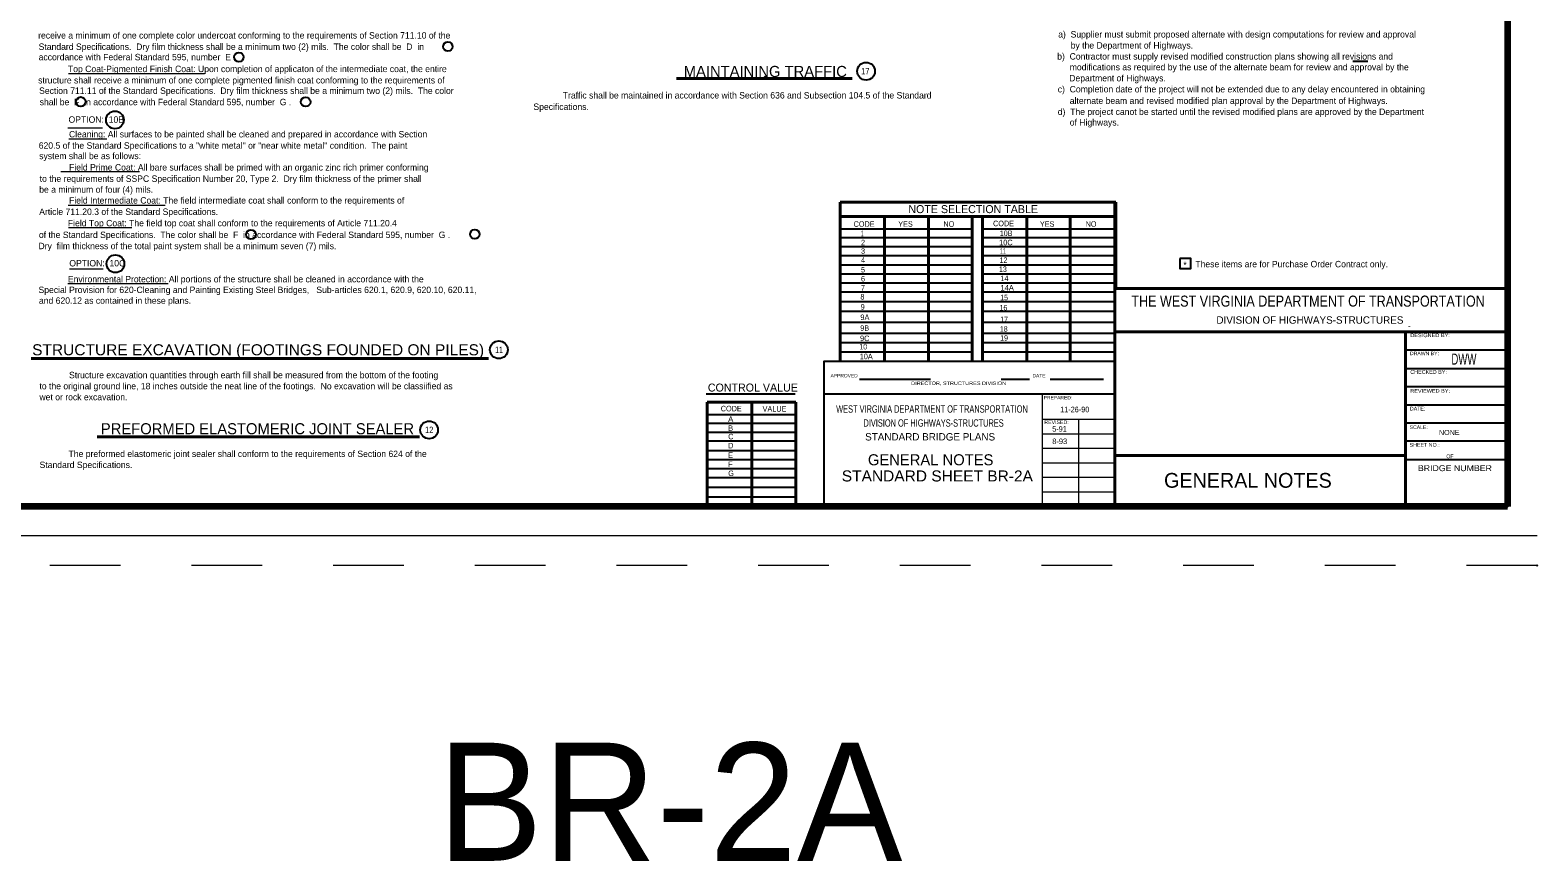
# Model space of a CAD drawing. Extents: x -2.94 to 3.45, y 0.57 to 4.
# Drawn here: x 1.326 to 3.455, y 1.205 to 2.377 of the extents above; entities that cross this region are included whole.
import ezdxf
from ezdxf.enums import TextEntityAlignment as Align

# ---------------------------------------------------------------- set-up
doc = ezdxf.new("R2010")
doc.units = 0
doc.header["$LTSCALE"] = 0.0036
doc.header["$PDMODE"] = 32
doc.header["$PDSIZE"] = 0.0018
doc.linetypes.add('DOTTED', pattern=[1.5, 0.3, -1.2])
doc.linetypes.add('LONG_DASHED', pattern=[7.5, 6, -1.5])
for name, color, linetype, lineweight in [('1', 7, 'Continuous', 13), ('3', 7, 'Continuous', 25), ('61', 7, 'Continuous', 25)]:
    doc.layers.add(name, color=color, linetype=linetype, lineweight=lineweight)

msp = doc.modelspace()

# ---------------------------------------------------------------- linework, layer by layer
at = {"layer": '1', "lineweight": 158}
for p, q in [((3.411833, 3.455), (3.411833, 1.705)), ((3.411833, 1.705), (0.599333, 1.705))]:
    msp.add_line(p, q, dxfattribs=at)
at = {"layer": '1', "lineweight": 25}
for p, q in [((3.273583, 1.9585), (3.273583, 1.959)), ((3.267667, 1.92575), (3.411833, 1.92575)), ((2.446917, 1.910083), (2.857583, 1.910083)), ((3.267667, 1.899833), (3.411833, 1.899833)), ((3.267667, 1.874), (3.411833, 1.874)), ((2.446917, 1.863667), (2.857583, 1.863667)), ((3.267667, 1.8485), (3.411833, 1.8485)), ((3.267667, 1.82275), (3.411833, 1.82275)), ((3.267667, 1.797333), (3.411833, 1.797333)), ((3.267667, 1.771333), (3.411833, 1.771333))]:
    msp.add_line(p, q, dxfattribs=at)
at = {"layer": '1', "lineweight": 40}
for p, q in [((2.857583, 1.951167), (3.411833, 1.951167)), ((3.267667, 1.951167), (3.267667, 1.705)), ((2.857583, 1.77675), (3.267667, 1.77675))]:
    msp.add_line(p, q, dxfattribs=at)
at = {"layer": '1', "linetype": 'DOTTED', "lineweight": 25}
for p, q in [((2.497167, 1.884417), (2.736833, 1.884417)), ((2.766, 1.884417), (2.841333, 1.884417))]:
    msp.add_line(p, q, dxfattribs=at)
at = {"layer": '1'}
for p, q in [((2.755, 1.863667), (2.755, 1.705)), ((2.755, 1.828167), (2.857583, 1.828167)), ((2.80625, 1.828583), (2.80625, 1.705)), ((2.755, 1.807583), (2.857583, 1.807583)), ((2.755, 1.787), (2.857583, 1.787)), ((2.755, 1.7665), (2.857583, 1.7665)), ((2.755, 1.746083), (2.857583, 1.746083)), ((2.755, 1.7255), (2.857583, 1.7255)), ((3.45375, 1.66325), (0.45325, 1.66325))]:
    msp.add_line(p, q, dxfattribs=at)
at = {"layer": '1', "linetype": 'LONG_DASHED'}
msp.add_line((3.45375, 1.621583), (0.45325, 1.621583), dxfattribs=at)
at = {"layer": '1', "lineweight": 40}
msp.add_lwpolyline([(2.857583, 1.705), (2.857583, 2.012667), (3.411833, 2.012667)], dxfattribs=at)
at = {"layer": '1', "lineweight": 25}
msp.add_lwpolyline([(2.446917, 1.705), (2.446917, 1.910083), (2.857583, 1.910083)], dxfattribs=at)
at = {"layer": '1'}
for p in [(2.363917, 2.311083), (3.411833, 1.705), (3.45375, 1.621583)]:
    msp.add_point(p, dxfattribs=at)
at = {"layer": '3'}
msp.add_line((3.193667, 2.333333), (3.2145, 2.333333), dxfattribs=at)
at = {"layer": '3', "lineweight": 13}
for p, q in [((1.380333, 2.316083), (1.572, 2.316083)), ((1.379167, 2.239083), (1.42825, 2.239083)), ((1.380833, 2.223917), (1.434417, 2.223917)), ((1.36925, 2.177417), (1.480417, 2.177417)), ((1.3795, 2.129917), (1.516833, 2.129917)), ((1.38, 2.098583), (1.469667, 2.098583)), ((1.3815, 2.040083), (1.429167, 2.040083)), ((1.37925, 2.019667), (1.521083, 2.019667))]:
    msp.add_line(p, q, dxfattribs=at)
at = {"layer": '3', "lineweight": 40}
for p, q in [((2.23875, 2.308833), (2.486583, 2.308833)), ((1.327667, 1.913917), (1.972917, 1.913917)), ((1.420417, 1.803083), (1.875667, 1.803083))]:
    msp.add_line(p, q, dxfattribs=at)
at = {"layer": '3'}
msp.add_lwpolyline([(2.949333, 2.054917), (2.949333, 2.040667), (2.964917, 2.040667), (2.964917, 2.054917)], close=True, dxfattribs=at)
for centre, radius in [((1.62075, 2.339083), 0.006667), ((1.915833, 2.354), 0.006667), ((2.50625, 2.319167), 0.0125), ((1.397417, 2.276167), 0.006667), ((1.715, 2.275917), 0.006667), ((1.44575, 2.250417), 0.0125), ((1.637833, 2.088583), 0.006667), ((1.953833, 2.089083), 0.006667), ((1.446417, 2.047417), 0.0125), ((1.98775, 1.926083), 0.0125), ((1.889333, 1.812917), 0.0125)]:
    msp.add_circle(centre, radius, dxfattribs=at)
at = {"layer": '61', "lineweight": 40}
for p, q in [((2.469583, 2.134333), (2.469583, 1.910083)), ((2.469583, 2.134333), (2.858667, 2.134333)), ((2.4695, 2.113917), (2.858583, 2.113917)), ((2.532417, 1.910083), (2.532417, 2.11375)), ((2.594583, 1.910083), (2.594583, 2.113917)), ((2.655917, 1.910083), (2.655917, 2.114)), ((2.670417, 1.910083), (2.670417, 2.113833)), ((2.733167, 1.910083), (2.733167, 2.113833)), ((2.794583, 1.910083), (2.794583, 2.113917)), ((2.469583, 2.059833), (2.469583, 2.046667)), ((2.281917, 1.852083), (2.407, 1.852083)), ((2.282, 1.852167), (2.282, 1.705583)), ((2.407, 1.705583), (2.407, 1.852083)), ((2.344833, 1.7055), (2.344833, 1.851833)), ((2.282, 1.797917), (2.282, 1.784833)), ((2.282, 1.7055), (2.407, 1.7055))]:
    msp.add_line(p, q, dxfattribs=at)
at = {"layer": '61', "lineweight": 53}
msp.add_line((2.858583, 2.012667), (2.858583, 2.134333), dxfattribs=at)
at = {"layer": '61'}
for p, q in [((2.655917, 2.09625), (2.469417, 2.09625)), ((2.858583, 2.09625), (2.670333, 2.09625)), ((2.655917, 2.083833), (2.4695, 2.083833)), ((2.656, 2.07125), (2.469583, 2.07125)), ((2.858583, 2.083833), (2.670333, 2.083833)), ((2.858583, 2.07125), (2.670333, 2.07125)), ((2.4695, 2.045833), (2.656, 2.045833)), ((2.656, 2.058833), (2.469583, 2.058833)), ((2.469583, 2.058167), (2.469583, 2.042583)), ((2.858583, 2.058833), (2.670333, 2.058833)), ((2.670333, 2.045833), (2.857583, 2.045833)), ((2.4695, 2.033083), (2.655917, 2.033083)), ((2.469583, 2.0335), (2.469583, 2.020333)), ((2.670333, 2.033083), (2.857583, 2.033083)), ((2.469583, 2.02075), (2.469583, 1.9825)), ((2.469583, 2.020333), (2.655917, 2.020333)), ((2.469583, 2.007583), (2.656, 2.007583)), ((2.469583, 2.007167), (2.469583, 1.994)), ((2.670333, 2.020333), (2.85675, 2.020333)), ((2.670333, 2.007583), (2.858417, 2.007583)), ((2.469583, 1.994), (2.656, 1.994)), ((2.469583, 1.9805), (2.656, 1.9805)), ((2.670333, 1.9805), (2.857583, 1.9805)), ((2.670417, 1.994), (2.857583, 1.994)), ((2.469583, 1.964833), (2.656, 1.964833)), ((2.670333, 1.964833), (2.857583, 1.964833)), ((2.469583, 1.94925), (2.656, 1.94925)), ((2.670333, 1.94925), (2.857583, 1.94925)), ((2.469583, 1.93625), (2.656, 1.93625)), ((2.469583, 1.92325), (2.656, 1.92325)), ((2.670333, 1.93625), (2.857583, 1.93625)), ((2.670333, 1.92325), (2.857583, 1.92325)), ((2.2805, 1.86375), (2.40625, 1.86375)), ((2.407, 1.834333), (2.281833, 1.834333)), ((2.407, 1.821917), (2.281917, 1.821917)), ((2.407, 1.809333), (2.282, 1.809333)), ((2.407, 1.796917), (2.282, 1.796917)), ((2.282, 1.796333), (2.282, 1.780667)), ((2.281917, 1.784), (2.407, 1.784)), ((2.281917, 1.77125), (2.407, 1.77125)), ((2.282, 1.771583), (2.282, 1.7585)), ((2.282, 1.758833), (2.282, 1.720583)), ((2.282, 1.7585), (2.407, 1.7585)), ((2.282, 1.74575), (2.407, 1.74575)), ((2.282, 1.745333), (2.282, 1.732167)), ((2.282, 1.732167), (2.407, 1.732167)), ((2.282, 1.731833), (2.282, 1.705583)), ((2.282, 1.718667), (2.407, 1.718667))]:
    msp.add_line(p, q, dxfattribs=at)

# ---------------------------------------------------------------- texts
at = {"layer": '1'}
for s, height, p in [('Field Top Coat: The field top coat shall conform to the requirements of Article 711.20.4', 0.009083, (1.379333, 2.10025)), ('of the Standard Specifications.  The color shall be  F  in accordance with Federal Standard 595, number  G .', 0.009083, (1.338417, 2.08375)), ('Dry  film thickness of the total paint system shall be a minimum seven (7) mils.', 0.009083, (1.337833, 2.068)), ('OPTION:  10C', 0.009083, (1.381333, 2.043667)), ('Environmental Protection: All portions of the structure shall be cleaned in accordance with the ', 0.009083, (1.379333, 2.021167)), ('Special Provision for 620-Cleaning and Painting Existing Steel Bridges,   Sub-articles 620.1, 620.9, 620.10, 620.11,', 0.009083, (1.337833, 2.006083)), ('and 620.12 as contained in these plans.', 0.009083, (1.338417, 1.990917)), ('DATE:', 0.005335, (3.274083, 1.840333)), ('REVISED:', 0.005335, (2.757917, 1.821167)), ('NONE', 0.007251, (3.315083, 1.805667))]:
    msp.add_text(s, height=height, dxfattribs=at).set_placement(p)
for s, height, width, p in [('THE WEST VIRGINIA DEPARTMENT OF TRANSPORTATION', 0.01558, 0.85, (3.13025, 1.986917)), ('WEST VIRGINIA DEPARTMENT OF TRANSPORTATION', 0.01042, 0.75, (2.599292, 1.83725)), ('DIVISION OF HIGHWAYS-STRUCTURES', 0.01042, 0.75, (2.601542, 1.8175)), ('BRIDGE NUMBER', 0.008416, 1.1, (3.337542, 1.75475))]:
    msp.add_text(s, height=height, dxfattribs=dict(at, width=width)).set_placement(p, align=Align.CENTER)
msp.add_text('DIVISION OF HIGHWAYS-STRUCTURES ', height=0.01042, dxfattribs=at).set_placement((3.134792, 1.962833), align=Align.CENTER)
for s, height, width, p in [('DESIGNED BY:', 0.005335, 1.1, (3.274583, 1.943833)), ('DRAWN BY:', 0.004918, 1.1, (3.274083, 1.918417)), ('DWW', 0.01558, 0.65, (3.332583, 1.905083)), ('CHECKED BY:', 0.005419, 1.05, (3.274583, 1.892)), ('APPROVED', 0.004917, 1.05, (2.456083, 1.887083)), ('DIRECTOR, STRUCTURES DIVISION', 0.004835, 1.2, (2.569917, 1.876417)), ('DATE', 0.004917, 1.05, (2.741167, 1.887083)), ('PREPARED:', 0.004751, 1.1, (2.756917, 1.856)), ('REVIEWED BY:', 0.004835, 1.2, (3.274583, 1.865667)), ('SCALE:', 0.004918, 1.1, (3.273583, 1.814333)), ('SHEET NO.:', 0.005335, 1.05, (3.273583, 1.789083)), ('OF', 0.005419, 0.85, (3.325417, 1.772917))]:
    msp.add_text(s, height=height, dxfattribs=dict(at, width=width)).set_placement(p)
at = {"layer": '3'}
for s, height, p in [('receive a minimum of one complete color undercoat conforming to the requirements of Section 711.10 of the ', 0.009083, (1.337333, 2.36525)), ('a)  Supplier must submit proposed alternate with design computations for review and approval', 0.009083, (2.777417, 2.36675)), ('accordance with Federal Standard 595, number  E .', 0.009083, (1.338, 2.334583)), ('Standard Specifications.  Dry film thickness shall be a minimum two (2) mils.  The color shall be  D  in ', 0.009083, (1.338, 2.34925)), ('b)  Contractor must supply revised modified construction plans showing all revisions and', 0.009083, (2.776083, 2.335583)), ('by the Department of Highways.', 0.009083, (2.795083, 2.351167)), ('Top Coat-Pigmented Finish Coat: Upon completion of applicaton of the intermediate coat, the entire', 0.009083, (1.379417, 2.317917)), ('modifications as required by the use of the alternate beam for review and approval by the', 0.009083, (2.79375, 2.320417)), ('structure shall receive a minimum of one complete pigmented finish coat conforming to the requirements of ', 0.009083, (1.337333, 2.301917)), ('Department of Highways.', 0.009083, (2.793083, 2.304833)), ('Section 711.11 of the Standard Specifications.  Dry film thickness shall be a minimum two (2) mils.  The color', 0.009083, (1.338667, 2.287167)), ('shall be  F  in accordance with Federal Standard 595, number  G .', 0.009083, (1.3395, 2.271167)), ('Traffic shall be maintained in accordance with Section 636 and Subsection 104.5 of the Standard', 0.009083, (2.078, 2.280667)), ('c)  Completion date of the project will not be extended due to any delay encountered in obtaining', 0.009083, (2.776833, 2.28925)), ('alternate beam and revised modified plan approval by the Department of Highways.', 0.009083, (2.79375, 2.273)), ('Specifications.', 0.009083, (2.036583, 2.2645)), ('d)  The project canot be started until the revised modified plans are approved by the Department', 0.009083, (2.776833, 2.257417)), ('OPTION:  10B', 0.009083, (1.38025, 2.246417)), ('Cleaning: All surfaces to be painted shall be cleaned and prepared in accordance with Section', 0.009083, (1.380917, 2.22575)), ('of Highways.', 0.009083, (2.79375, 2.2425)), ('620.5 of the Standard Specifications to a "white metal" or "near white metal" condition.  The paint ', 0.009083, (1.338167, 2.20975)), ('system shall be as follows:', 0.009083, (1.338833, 2.195083)), ('to the requirements of SSPC Specification Number 20, Type 2.  Dry film thickness of the primer shall', 0.009083, (1.3395, 2.163)), ('Field Prime Coat: All bare surfaces shall be primed with an organic zinc rich primer conforming  ', 0.009083, (1.380917, 2.179)), ('be a minimum of four (4) mils.', 0.009083, (1.338833, 2.147667)), ('Field Intermediate Coat: The field intermediate coat shall conform to the requirements of', 0.009083, (1.380917, 2.132333)), ('Article 711.20.3 of the Standard Specifications.', 0.009083, (1.338833, 2.116333)), ('*', 0.009083, (2.954167, 2.041167)), ('These items are for Purchase Order Contract only.', 0.009083, (2.971083, 2.042417)), ('Structure excavation quantities through earth fill shall be measured from the bottom of the footing ', 0.009083, (1.380917, 1.885833)), ('to the original ground line, 18 inches outside the neat line of the footings.  No excavation will be classiified as', 0.009083, (1.339167, 1.87025)), ('wet or rock excavation.', 0.009083, (1.339167, 1.85475)), ('STANDARD BRIDGE PLANS', 0.01042, (2.504917, 1.798)), ('Standard Specifications.', 0.009083, (1.339333, 1.759083)), ('The preformed elastomeric joint sealer shall conform to the requirements of Section 624 of the', 0.009083, (1.38025, 1.774667)), ('GENERAL NOTES', 0.01558, (2.508833, 1.763)), ('GENERAL NOTES', 0.02083, (2.926917, 1.731333))]:
    msp.add_text(s, height=height, dxfattribs=at).set_placement(p)
for s, height, p in [('MAINTAINING TRAFFIC', 0.01558, (2.363958, 2.311083)), ('PREFORMED ELASTOMERIC JOINT SEALER', 0.01558, (1.646958, 1.806833)), ('BR-2A', 0.1667, (2.229167, 1.20475))]:
    msp.add_text(s, height=height, dxfattribs=at).set_placement(p, align=Align.CENTER)
for s, height, width, p in [('17', 0.009083, 0.8, (2.505167, 2.314667)), ('STRUCTURE EXCAVATION (FOOTINGS FOUNDED ON PILES)', 0.01558, 1.05, (1.647875, 1.91825)), ('11', 0.009083, 0.65, (1.988, 1.9215)), ('12', 0.009083, 0.8, (1.889375, 1.808417))]:
    msp.add_text(s, height=height, dxfattribs=dict(at, width=width)).set_placement(p, align=Align.CENTER)
at = {"layer": '3', "width": 1.05}
msp.add_text('STANDARD SHEET BR-2A', height=0.01558, dxfattribs=at).set_placement((2.471917, 1.740167))
at = {"layer": '61'}
for s, height, p in [('NOTE SELECTION TABLE', 0.01125, (2.565917, 2.118917)), ('9A', 0.007833, (2.498167, 1.968)), ('CONTROL VALUE', 0.01125, (2.282833, 1.867083)), ('8-93', 0.007833, (2.769083, 1.792917))]:
    msp.add_text(s, height=height, dxfattribs=at).set_placement(p)
for s, height, width, p in [('CODE', 0.007833, 0.9, (2.488667, 2.099583)), ('YES', 0.007833, 0.9, (2.551667, 2.099583)), ('NO', 0.007833, 0.95, (2.615417, 2.099583)), ('CODE', 0.007833, 0.9, (2.6855, 2.100417)), ('YES', 0.007833, 0.9, (2.751667, 2.099583)), ('NO', 0.007833, 0.95, (2.816167, 2.099583)), ('1', 0.007833, 0.5, (2.499083, 2.086167)), ('10B', 0.007833, 0.85, (2.694917, 2.0865)), ('3', 0.007833, 0.9, (2.499083, 2.0615)), ('2', 0.007833, 0.85, (2.499083, 2.073417)), ('10C', 0.007833, 0.8, (2.694, 2.073583)), ('11', 0.007833, 0.6, (2.695, 2.0615)), ('4', 0.007833, 0.9, (2.499083, 2.04875)), ('13', 0.007833, 0.75, (2.694, 2.035833)), ('12', 0.007833, 0.75, (2.69475, 2.048583)), ('5', 0.007833, 0.9, (2.499083, 2.035167)), ('6', 0.007833, 0.9, (2.499083, 2.022417)), ('14', 0.00775, 0.8, (2.69575, 2.022917)), ('8', 0.007833, 0.9, (2.49825, 1.996917)), ('7', 0.007833, 0.85, (2.499083, 2.009667)), ('15', 0.007833, 0.75, (2.695583, 1.995917)), ('14A', 0.00775, 0.9, (2.695917, 2.009583)), ('9', 0.007833, 0.9, (2.498583, 1.982667)), ('16', 0.007833, 0.75, (2.694667, 1.9815)), ('9B', 0.007833, 0.9, (2.498, 1.95275)), ('18', 0.007833, 0.75, (2.695167, 1.951417)), ('17', 0.007833, 0.75, (2.695667, 1.965)), ('9C', 0.007833, 0.9, (2.49775, 1.93825)), ('19', 0.007833, 0.75, (2.695583, 1.93875)), ('10', 0.007833, 0.75, (2.49675, 1.9265)), ('10A', 0.007833, 0.9, (2.497333, 1.91275)), ('CODE', 0.007833, 0.9, (2.301083, 1.839083)), ('A', 0.00775, 1.05, (2.3115, 1.824333)), ('VALUE', 0.007833, 0.95, (2.360083, 1.838667)), ('11-26-90', 0.007833, 0.95, (2.78025, 1.837833)), ('B', 0.00775, 0.85, (2.3115, 1.811583)), ('5-91', 0.007833, 0.9, (2.769083, 1.810417)), ('C', 0.007833, 0.8, (2.3115, 1.799583)), ('D', 0.007833, 0.9, (2.3115, 1.786833)), ('E', 0.00775, 0.8, (2.3115, 1.773333)), ('F', 0.00775, 0.8, (2.3115, 1.760583)), ('G', 0.00775, 0.85, (2.3115, 1.747833))]:
    msp.add_text(s, height=height, dxfattribs=dict(at, width=width)).set_placement(p)

doc.saveas('drawing.dxf')
